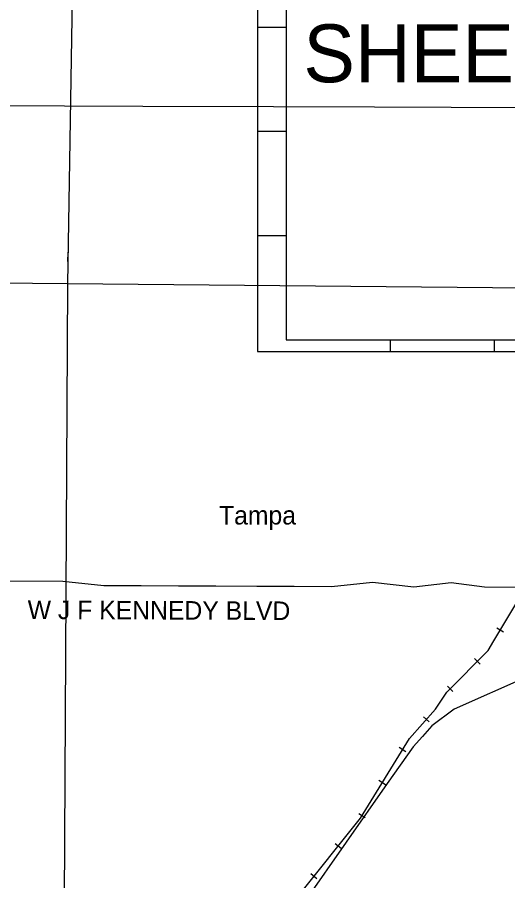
# Model space of a CAD drawing. Extents: x 492225 to 553725, y 1303773 to 1347273.
# Drawn here: x 499152 to 503393, y 1310432 to 1317894 of the extents above; entities that cross this region are included whole.
import ezdxf

# ---------------------------------------------------------------- set-up
doc = ezdxf.new("R2010")
doc.units = 0
for name, color, linetype in [('Level 1', 7, 'Continuous'), ('Level 13', 7, 'Continuous'), ('Level 22', 7, 'Continuous'), ('Level 28', 7, 'Continuous'), ('Level 37', 7, 'Continuous'), ('Level 44', 7, 'Continuous')]:
    doc.layers.add(name, color=color, linetype=linetype)

msp = doc.modelspace()

# ---------------------------------------------------------------- linework, layer by layer
at = {"layer": 'Level 1'}
for p, q in [((499675.349, 1320917.678), (499586.966, 1315590.825)), ((501478.147, 1317806.301), (501228.147, 1317806.301)), ((501478.147, 1316906.301), (501228.147, 1316906.301)), ((501478.147, 1316006.301), (501228.147, 1316006.301)), ((499588.519, 1315862.79), (499588.061, 1315782.702)), ((499586.966, 1315590.825), (495463.793, 1315618.6072)), ((499586.966, 1315590.825), (499556.27, 1310217.447)), ((504928.709, 1315540.774), (499586.966, 1315590.825)), ((502378.147, 1315006.301), (502378.147, 1315106.301)), ((503278.147, 1315006.301), (503278.147, 1315106.301))]:
    msp.add_line(p, q, dxfattribs=at)
for points in [[(501228.147, 1315006.301), (509228.147, 1315006.301), (509228.147, 1320606.301), (501228.147, 1320606.301)], [(501478.147, 1315106.301), (509128.147, 1315106.301), (509128.147, 1320506.301), (501478.147, 1320506.301)]]:
    msp.add_lwpolyline(points, close=True, dxfattribs=at)
at = {"layer": 'Level 13'}
for p, q in [((499561.398, 1317126.942), (498883.449, 1317129.632)), ((500239.345, 1317124.263), (499561.398, 1317126.942)), ((501369.259, 1317119.822), (500239.345, 1317124.263)), ((502240.905, 1317116.419), (501369.259, 1317119.822)), ((503596.799, 1317111.164), (502240.905, 1317116.419))]:
    msp.add_line(p, q, dxfattribs=at)
at = {"layer": 'Level 22'}
for p, q in [((499545.094, 1313018.819), (499060.795, 1313020.741)), ((499900.103, 1312981.059), (499545.094, 1313018.819)), ((502224.88, 1313008.3), (501869.586, 1312973.328)), ((502579.892, 1312970.564), (502224.88, 1313008.3)), ((502902.899, 1313005.667), (502579.892, 1312970.564)), ((503193.337, 1312968.187), (502902.899, 1313005.667)), ((500222.969, 1312979.786), (499900.103, 1312981.059)), ((500545.835, 1312978.514), (500222.969, 1312979.786)), ((500868.701, 1312977.245), (500545.835, 1312978.514)), ((501223.854, 1312975.853), (500868.701, 1312977.245)), ((501546.72, 1312974.589), (501223.854, 1312975.853)), ((501869.586, 1312973.328), (501546.72, 1312974.589)), ((503548.489, 1312966.815), (503193.337, 1312968.187)), ((503577.825, 1312203.236), (502930.952, 1311914.892)), ((502930.952, 1311914.892), (502736.662, 1311770.223)), ((502736.662, 1311770.223), (502655.589, 1311679.648)), ((502655.589, 1311679.648), (502574.517, 1311589.074)), ((502574.517, 1311589.074), (502351.784, 1311271.828)), ((502351.784, 1311271.828), (501632.908, 1310247.587))]:
    msp.add_line(p, q, dxfattribs=at)
at = {"layer": 'Level 37'}
for p, q in [((503356.274, 1312579.348), (503298.461, 1312613.88)), ((503154.67, 1312304.821), (503106.683, 1312352.066)), ((502919.746, 1312066.203), (502871.759, 1312113.448)), ((502715.195, 1311804.348), (502665.019, 1311849.259)), ((502511.872, 1311547.5), (502454.459, 1311582.695)), ((502336.866, 1311262.016), (502279.454, 1311297.21)), ((502161.86, 1310976.531), (502104.448, 1311011.727)), ((501952.649, 1310709.929), (501900.092, 1310752.032)), ((501743.299, 1310448.586), (501690.742, 1310490.687))]:
    msp.add_line(p, q, dxfattribs=at)
msp.add_lwpolyline([(501568.472, 1310284.193), (502120.077, 1310972.797), (502542.512, 1311661.909), (502769.514, 1311915.518), (502866.942, 1312060.562), (503223.511, 1312422.738), (503273.558, 1312506.525), (503548.489, 1312966.815)], dxfattribs=at)

# ---------------------------------------------------------------- texts
at = {"layer": 'Level 1'}
msp.add_text('SHEET 3', height=500, dxfattribs=at).set_placement((501626.284, 1317332.615))
at = {"layer": 'Level 28'}
msp.add_text('W J F KENNEDY BLVD', height=159.999996, rotation=359.77222222, dxfattribs=at).set_placement((499242.285, 1312694.181))
at = {"layer": 'Level 44'}
msp.add_text('Tampa', height=160, dxfattribs=at).set_placement((500896.668, 1313510.712))

doc.saveas('drawing.dxf')
